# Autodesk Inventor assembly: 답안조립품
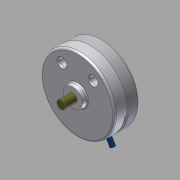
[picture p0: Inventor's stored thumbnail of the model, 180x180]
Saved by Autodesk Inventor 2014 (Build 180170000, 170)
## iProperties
Created: 2015-06
Part Number: 답안조립품
Document SubType Name: Assembly
Designer: MYHOME
Author: MYHOME
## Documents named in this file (10)
- C:\Documents and Settings\MYHOME\바탕 화면\전정우\답안조립품.iam
- C:\Documents and Settings\MYHOME\바탕 화면\전정우\본체.ipt
- C:\Documents and Settings\MYHOME\바탕 화면\전정우\베어링62_22.ipt
- C:\Documents and Settings\MYHOME\바탕 화면\전정우\축.ipt
- C:\Documents and Settings\MYHOME\바탕 화면\전정우\멈춤링.ipt
- C:\Documents and Settings\MYHOME\바탕 화면\전정우\슬라이더2.ipt
- C:\Documents and Settings\MYHOME\바탕 화면\전정우\슬라이더.ipt
- C:\Documents and Settings\MYHOME\바탕 화면\전정우\평행핀.ipt
- C:\Documents and Settings\MYHOME\바탕 화면\전정우\덮개.ipt
- C:\Documents and Settings\MYHOME\바탕 화면\전정우\M10x35.ipt
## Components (7 placed, 4 different names)
1. KS B 2023 62/22 - 22 x 50 x 14:1 — 플러쉬:1
2. KS B 1336 22 x 1.2:1
3. KS B 1336 22 x 1.2:2
4. KS B 1320 B B 5 x  20:1
5. KS B 2023 62/22 - 22 x 50 x 14:2
6. KS B 1003 - 미터 M 10 x 35:1
7. KS B 1003 - 미터 M 10 x 35:2
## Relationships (1: Flush 1)
- 플러쉬:1 [Flush]: KS B 2023 62/22 - 22 x 50 x 14:1
